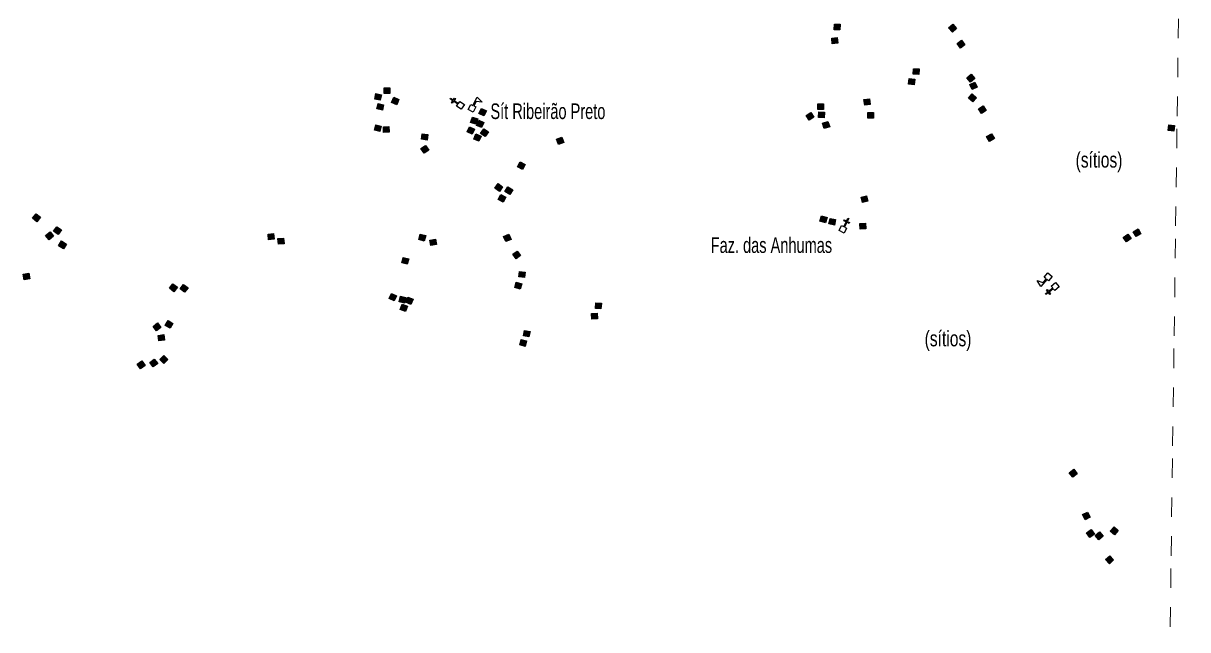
# Model space of a CAD drawing. Extents: x 679 to 705, y 7427.4 to 7455.4.
# Drawn here: x 698.81 to 704.8, y 7433.76 to 7436.88 of the extents above; entities that cross this region are included whole.
import ezdxf

# ---------------------------------------------------------------- set-up
doc = ezdxf.new("R2010")
doc.units = 0
doc.header["$LTSCALE"] = 0.032
doc.linetypes.add('SHORT_DASHED', pattern=[2.7, 1.5, -1.2])
for name, color, linetype, lineweight in [('2', 7, 'Continuous', 25), ('4', 7, 'Continuous', 25), ('58', 7, 'SHORT_DASHED', 13), ('6', 7, 'Continuous', 25)]:
    doc.layers.add(name, color=color, linetype=linetype, lineweight=lineweight)
doc.layers.add('61', color=7, linetype='Continuous')

msp = doc.modelspace()

# ---------------------------------------------------------------- hatches: boundary and pattern name
at = {"layer": '2'}
for points in [[(703.0125, 7436.8742), (703.0116, 7436.8452), (702.9826, 7436.8461), (702.9835, 7436.8751)], [(703.592, 7436.8745), (703.6113, 7436.8529), (703.5897, 7436.8335), (703.5704, 7436.8551)], [(702.9982, 7436.8054), (703.0006, 7436.7765), (702.9717, 7436.7741), (702.9693, 7436.803)], [(703.6374, 7436.7914), (703.6546, 7436.768), (703.6312, 7436.7508), (703.614, 7436.7742)], [(703.4182, 7436.6445), (703.417, 7436.6155), (703.388, 7436.6167), (703.3892, 7436.6456)], [(703.6862, 7436.6167), (703.7053, 7436.5949), (703.6834, 7436.5758), (703.6643, 7436.5977)], [(700.6981, 7436.5466), (700.6981, 7436.5176), (700.6691, 7436.5176), (700.6691, 7436.5466)], [(703.3971, 7436.5908), (703.3927, 7436.5622), (703.3641, 7436.5665), (703.3684, 7436.5952)], [(703.7056, 7436.5763), (703.7178, 7436.55), (703.6915, 7436.5378), (703.6793, 7436.5641)], [(700.6542, 7436.5114), (700.6486, 7436.4829), (700.6201, 7436.4886), (700.6258, 7436.5171)], [(700.7448, 7436.4865), (700.733, 7436.46), (700.7065, 7436.4718), (700.7183, 7436.4983)], [(703.1634, 7436.4909), (703.1678, 7436.4622), (703.1392, 7436.4578), (703.1348, 7436.4865)], [(703.6923, 7436.5155), (703.7138, 7436.4961), (703.6944, 7436.4745), (703.6729, 7436.4939)], [(700.6657, 7436.4604), (700.6594, 7436.4321), (700.6311, 7436.4385), (700.6375, 7436.4667)], [(701.1683, 7436.4413), (701.1943, 7436.4284), (701.1813, 7436.4024), (701.1553, 7436.4154)], [(702.8621, 7436.421), (702.8781, 7436.3969), (702.854, 7436.3808), (702.8379, 7436.4049)], [(702.9268, 7436.4651), (702.9268, 7436.4361), (702.8978, 7436.4361), (702.8978, 7436.4651)], [(702.9318, 7436.4221), (702.9301, 7436.3931), (702.9012, 7436.3948), (702.9029, 7436.4238)], [(703.184, 7436.4201), (703.184, 7436.3911), (703.155, 7436.3911), (703.155, 7436.4201)], [(703.7477, 7436.4548), (703.7638, 7436.4306), (703.7396, 7436.4145), (703.7236, 7436.4387)], [(700.6532, 7436.3505), (700.6465, 7436.3223), (700.6183, 7436.329), (700.625, 7436.3572)], [(701.1222, 7436.3967), (701.1497, 7436.3875), (701.1406, 7436.36), (701.1131, 7436.3692)], [(701.1547, 7436.3805), (701.1813, 7436.369), (701.1697, 7436.3424), (701.1431, 7436.3539)], [(702.9498, 7436.3744), (702.959, 7436.3469), (702.9315, 7436.3378), (702.9223, 7436.3653)], [(704.7321, 7436.3536), (704.7284, 7436.3248), (704.6996, 7436.3285), (704.7033, 7436.3573)], [(700.6933, 7436.3475), (700.6945, 7436.3186), (700.6656, 7436.3173), (700.6644, 7436.3463)], [(700.8936, 7436.307), (700.8895, 7436.2783), (700.8607, 7436.2824), (700.8648, 7436.3111)], [(701.1076, 7436.3471), (701.1338, 7436.3344), (701.1211, 7436.3083), (701.095, 7436.3209)], [(701.1404, 7436.3101), (701.1671, 7436.299), (701.156, 7436.2722), (701.1292, 7436.2833)], [(701.1807, 7436.3366), (701.2046, 7436.3202), (701.1882, 7436.2963), (701.1643, 7436.3127)], [(703.7907, 7436.3112), (703.8057, 7436.2863), (703.7808, 7436.2714), (703.7659, 7436.2963)], [(700.8817, 7436.2509), (700.8978, 7436.2268), (700.8737, 7436.2107), (700.8576, 7436.2348)], [(701.5818, 7436.2931), (701.5916, 7436.2658), (701.5643, 7436.256), (701.5545, 7436.2833)], [(701.3685, 7436.1673), (701.3939, 7436.1533), (701.38, 7436.1279), (701.3546, 7436.1418)], [(701.254, 7436.0553), (701.2777, 7436.0386), (701.261, 7436.0149), (701.2373, 7436.0316)], [(701.2686, 7435.9985), (701.2941, 7435.9848), (701.2804, 7435.9592), (701.2549, 7435.9729)], [(701.3048, 7436.0382), (701.3295, 7436.023), (701.3144, 7435.9983), (701.2896, 7436.0134)], [(703.1488, 7435.9926), (703.1559, 7435.9644), (703.1277, 7435.9574), (703.1207, 7435.9855)], [(698.879, 7435.8994), (698.9017, 7435.8814), (698.8836, 7435.8587), (698.8609, 7435.8767)], [(702.9453, 7435.8811), (702.9368, 7435.8534), (702.9091, 7435.8619), (702.9176, 7435.8896)], [(698.986, 7435.8332), (699.0098, 7435.8165), (698.9931, 7435.7928), (698.9694, 7435.8094)], [(702.9896, 7435.8697), (702.9831, 7435.8414), (702.9548, 7435.8478), (702.9613, 7435.8761)], [(703.1431, 7435.8515), (703.1453, 7435.8226), (703.1164, 7435.8204), (703.1142, 7435.8493)], [(704.5444, 7435.8217), (704.559, 7435.7966), (704.5339, 7435.782), (704.5193, 7435.8071)], [(698.9508, 7435.8067), (698.9689, 7435.7841), (698.9462, 7435.7659), (698.9281, 7435.7886)], [(699.0106, 7435.7599), (699.0349, 7435.7442), (699.0193, 7435.7198), (698.9949, 7435.7355)], [(700.1004, 7435.7985), (700.1035, 7435.7696), (700.0747, 7435.7665), (700.0716, 7435.7953)], [(700.1514, 7435.7742), (700.1537, 7435.7453), (700.1248, 7435.743), (700.1225, 7435.7719)], [(700.8824, 7435.7872), (700.8743, 7435.7593), (700.8465, 7435.7674), (700.8545, 7435.7952)], [(700.9326, 7435.7697), (700.9377, 7435.7412), (700.9092, 7435.7361), (700.904, 7435.7646)], [(701.3097, 7435.7942), (701.3208, 7435.7673), (701.294, 7435.7563), (701.2829, 7435.7831)], [(704.4918, 7435.7954), (704.509, 7435.772), (704.4856, 7435.7548), (704.4684, 7435.7782)], [(701.3532, 7435.7082), (701.3701, 7435.6846), (701.3466, 7435.6677), (701.3296, 7435.6912)], [(700.795, 7435.6681), (700.7877, 7435.6401), (700.7596, 7435.6474), (700.7669, 7435.6754)], [(698.842, 7435.5938), (698.8466, 7435.5651), (698.8179, 7435.5606), (698.8134, 7435.5892)], [(701.3935, 7435.6), (701.39, 7435.5712), (701.3612, 7435.5746), (701.3647, 7435.6034)], [(699.5826, 7435.5394), (699.6056, 7435.5219), (699.5881, 7435.4988), (699.565, 7435.5164)], [(699.6378, 7435.5367), (699.6605, 7435.5186), (699.6423, 7435.4959), (699.6197, 7435.5141)], [(701.3756, 7435.5398), (701.3676, 7435.5119), (701.3397, 7435.5199), (701.3477, 7435.5477)], [(700.6941, 7435.4639), (700.7062, 7435.4903), (700.7325, 7435.4782), (700.7204, 7435.4518)], [(700.7806, 7435.4685), (700.7736, 7435.4403), (700.7454, 7435.4474), (700.7525, 7435.4755)], [(700.8171, 7435.4603), (700.8059, 7435.4335), (700.7791, 7435.4447), (700.7903, 7435.4714)], [(700.7887, 7435.4244), (700.7785, 7435.3972), (700.7514, 7435.4074), (700.7615, 7435.4345)], [(701.7851, 7435.4401), (701.7832, 7435.4111), (701.7543, 7435.413), (701.7562, 7435.4419)], [(699.5576, 7435.3503), (699.5829, 7435.3362), (699.5689, 7435.3108), (699.5435, 7435.3249)], [(701.7642, 7435.3879), (701.765, 7435.3589), (701.736, 7435.3581), (701.7352, 7435.3871)], [(699.5035, 7435.3383), (699.5213, 7435.3154), (699.4984, 7435.2976), (699.4806, 7435.3205)], [(701.4185, 7435.2947), (701.413, 7435.2663), (701.3845, 7435.2718), (701.39, 7435.3003)], [(699.5353, 7435.2784), (699.5393, 7435.2497), (699.5105, 7435.2458), (699.5066, 7435.2745)], [(701.401, 7435.2457), (701.3933, 7435.2177), (701.3654, 7435.2254), (701.373, 7435.2534)], [(699.5362, 7435.1711), (699.5567, 7435.1506), (699.5362, 7435.1301), (699.5157, 7435.1506)], [(699.4226, 7435.1428), (699.4397, 7435.1194), (699.4162, 7435.1023), (699.3992, 7435.1258)], [(699.4867, 7435.1527), (699.5044, 7435.1298), (699.4815, 7435.1121), (699.4637, 7435.135)], [(704.2138, 7434.5859), (704.2314, 7434.5629), (704.2085, 7434.5452), (704.1908, 7434.5682)], [(704.285, 7434.3657), (704.2978, 7434.3396), (704.2717, 7434.3269), (704.259, 7434.353)], [(704.303, 7434.2765), (704.3198, 7434.2528), (704.2962, 7434.236), (704.2794, 7434.2596)], [(704.3466, 7434.264), (704.3651, 7434.2416), (704.3427, 7434.2231), (704.3242, 7434.2455)], [(704.4207, 7434.2907), (704.4426, 7434.2716), (704.4235, 7434.2497), (704.4016, 7434.2688)], [(704.3989, 7434.1415), (704.4186, 7434.1202), (704.3973, 7434.1006), (704.3776, 7434.1219)]]:
    msp.add_hatch(color=256, dxfattribs=at).paths.add_polyline_path(points)

# ---------------------------------------------------------------- linework, layer by layer
for points in [[(703.0125, 7436.8742), (703.0116, 7436.8452), (702.9826, 7436.8461), (702.9835, 7436.8751)], [(703.592, 7436.8745), (703.6113, 7436.8529), (703.5897, 7436.8335), (703.5704, 7436.8551)], [(702.9982, 7436.8054), (703.0006, 7436.7765), (702.9717, 7436.7741), (702.9693, 7436.803)], [(703.6374, 7436.7914), (703.6546, 7436.768), (703.6312, 7436.7508), (703.614, 7436.7742)], [(703.4182, 7436.6445), (703.417, 7436.6155), (703.388, 7436.6167), (703.3892, 7436.6456)], [(703.6862, 7436.6167), (703.7053, 7436.5949), (703.6834, 7436.5758), (703.6643, 7436.5977)], [(700.6981, 7436.5466), (700.6981, 7436.5176), (700.6691, 7436.5176), (700.6691, 7436.5466)], [(703.3971, 7436.5908), (703.3927, 7436.5622), (703.3641, 7436.5665), (703.3684, 7436.5952)], [(703.7056, 7436.5763), (703.7178, 7436.55), (703.6915, 7436.5378), (703.6793, 7436.5641)], [(700.6542, 7436.5114), (700.6486, 7436.4829), (700.6201, 7436.4886), (700.6258, 7436.5171)], [(700.7448, 7436.4865), (700.733, 7436.46), (700.7065, 7436.4718), (700.7183, 7436.4983)], [(703.1634, 7436.4909), (703.1678, 7436.4622), (703.1392, 7436.4578), (703.1348, 7436.4865)], [(703.6923, 7436.5155), (703.7138, 7436.4961), (703.6944, 7436.4745), (703.6729, 7436.4939)], [(700.6657, 7436.4604), (700.6594, 7436.4321), (700.6311, 7436.4385), (700.6375, 7436.4667)], [(701.1683, 7436.4413), (701.1943, 7436.4284), (701.1813, 7436.4024), (701.1553, 7436.4154)], [(702.8621, 7436.421), (702.8781, 7436.3969), (702.854, 7436.3808), (702.8379, 7436.4049)], [(702.9268, 7436.4651), (702.9268, 7436.4361), (702.8978, 7436.4361), (702.8978, 7436.4651)], [(702.9318, 7436.4221), (702.9301, 7436.3931), (702.9012, 7436.3948), (702.9029, 7436.4238)], [(703.184, 7436.4201), (703.184, 7436.3911), (703.155, 7436.3911), (703.155, 7436.4201)], [(703.7477, 7436.4548), (703.7638, 7436.4306), (703.7396, 7436.4145), (703.7236, 7436.4387)], [(700.6532, 7436.3505), (700.6465, 7436.3223), (700.6183, 7436.329), (700.625, 7436.3572)], [(701.1222, 7436.3967), (701.1497, 7436.3875), (701.1406, 7436.36), (701.1131, 7436.3692)], [(701.1547, 7436.3805), (701.1813, 7436.369), (701.1697, 7436.3424), (701.1431, 7436.3539)], [(702.9498, 7436.3744), (702.959, 7436.3469), (702.9315, 7436.3378), (702.9223, 7436.3653)], [(704.7321, 7436.3536), (704.7284, 7436.3248), (704.6996, 7436.3285), (704.7033, 7436.3573)], [(700.6933, 7436.3475), (700.6945, 7436.3186), (700.6656, 7436.3173), (700.6644, 7436.3463)], [(700.8936, 7436.307), (700.8895, 7436.2783), (700.8607, 7436.2824), (700.8648, 7436.3111)], [(701.1076, 7436.3471), (701.1338, 7436.3344), (701.1211, 7436.3083), (701.095, 7436.3209)], [(701.1404, 7436.3101), (701.1671, 7436.299), (701.156, 7436.2722), (701.1292, 7436.2833)], [(701.1807, 7436.3366), (701.2046, 7436.3202), (701.1882, 7436.2963), (701.1643, 7436.3127)], [(703.7907, 7436.3112), (703.8057, 7436.2863), (703.7808, 7436.2714), (703.7659, 7436.2963)], [(700.8817, 7436.2509), (700.8978, 7436.2268), (700.8737, 7436.2107), (700.8576, 7436.2348)], [(701.5818, 7436.2931), (701.5916, 7436.2658), (701.5643, 7436.256), (701.5545, 7436.2833)], [(701.3685, 7436.1673), (701.3939, 7436.1533), (701.38, 7436.1279), (701.3546, 7436.1418)], [(701.254, 7436.0553), (701.2777, 7436.0386), (701.261, 7436.0149), (701.2373, 7436.0316)], [(701.2686, 7435.9985), (701.2941, 7435.9848), (701.2804, 7435.9592), (701.2549, 7435.9729)], [(701.3048, 7436.0382), (701.3295, 7436.023), (701.3144, 7435.9983), (701.2896, 7436.0134)], [(703.1488, 7435.9926), (703.1559, 7435.9644), (703.1277, 7435.9574), (703.1207, 7435.9855)], [(698.879, 7435.8994), (698.9017, 7435.8814), (698.8836, 7435.8587), (698.8609, 7435.8767)], [(702.9453, 7435.8811), (702.9368, 7435.8534), (702.9091, 7435.8619), (702.9176, 7435.8896)], [(698.986, 7435.8332), (699.0098, 7435.8165), (698.9931, 7435.7928), (698.9694, 7435.8094)], [(702.9896, 7435.8697), (702.9831, 7435.8414), (702.9548, 7435.8478), (702.9613, 7435.8761)], [(703.1431, 7435.8515), (703.1453, 7435.8226), (703.1164, 7435.8204), (703.1142, 7435.8493)], [(704.5444, 7435.8217), (704.559, 7435.7966), (704.5339, 7435.782), (704.5193, 7435.8071)], [(698.9508, 7435.8067), (698.9689, 7435.7841), (698.9462, 7435.7659), (698.9281, 7435.7886)], [(699.0106, 7435.7599), (699.0349, 7435.7442), (699.0193, 7435.7198), (698.9949, 7435.7355)], [(700.1004, 7435.7985), (700.1035, 7435.7696), (700.0747, 7435.7665), (700.0716, 7435.7953)], [(700.1514, 7435.7742), (700.1537, 7435.7453), (700.1248, 7435.743), (700.1225, 7435.7719)], [(700.8824, 7435.7872), (700.8743, 7435.7593), (700.8465, 7435.7674), (700.8545, 7435.7952)], [(700.9326, 7435.7697), (700.9377, 7435.7412), (700.9092, 7435.7361), (700.904, 7435.7646)], [(701.3097, 7435.7942), (701.3208, 7435.7673), (701.294, 7435.7563), (701.2829, 7435.7831)], [(704.4918, 7435.7954), (704.509, 7435.772), (704.4856, 7435.7548), (704.4684, 7435.7782)], [(701.3532, 7435.7082), (701.3701, 7435.6846), (701.3466, 7435.6677), (701.3296, 7435.6912)], [(700.795, 7435.6681), (700.7877, 7435.6401), (700.7596, 7435.6474), (700.7669, 7435.6754)], [(698.842, 7435.5938), (698.8466, 7435.5651), (698.8179, 7435.5606), (698.8134, 7435.5892)], [(701.3935, 7435.6), (701.39, 7435.5712), (701.3612, 7435.5746), (701.3647, 7435.6034)], [(699.5826, 7435.5394), (699.6056, 7435.5219), (699.5881, 7435.4988), (699.565, 7435.5164)], [(699.6378, 7435.5367), (699.6605, 7435.5186), (699.6423, 7435.4959), (699.6197, 7435.5141)], [(701.3756, 7435.5398), (701.3676, 7435.5119), (701.3397, 7435.5199), (701.3477, 7435.5477)], [(700.6941, 7435.4639), (700.7062, 7435.4903), (700.7325, 7435.4782), (700.7204, 7435.4518)], [(700.7806, 7435.4685), (700.7736, 7435.4403), (700.7454, 7435.4474), (700.7525, 7435.4755)], [(700.8171, 7435.4603), (700.8059, 7435.4335), (700.7791, 7435.4447), (700.7903, 7435.4714)], [(700.7887, 7435.4244), (700.7785, 7435.3972), (700.7514, 7435.4074), (700.7615, 7435.4345)], [(701.7851, 7435.4401), (701.7832, 7435.4111), (701.7543, 7435.413), (701.7562, 7435.4419)], [(699.5576, 7435.3503), (699.5829, 7435.3362), (699.5689, 7435.3108), (699.5435, 7435.3249)], [(701.7642, 7435.3879), (701.765, 7435.3589), (701.736, 7435.3581), (701.7352, 7435.3871)], [(699.5035, 7435.3383), (699.5213, 7435.3154), (699.4984, 7435.2976), (699.4806, 7435.3205)], [(701.4185, 7435.2947), (701.413, 7435.2663), (701.3845, 7435.2718), (701.39, 7435.3003)], [(699.5353, 7435.2784), (699.5393, 7435.2497), (699.5105, 7435.2458), (699.5066, 7435.2745)], [(701.401, 7435.2457), (701.3933, 7435.2177), (701.3654, 7435.2254), (701.373, 7435.2534)], [(699.5362, 7435.1711), (699.5567, 7435.1506), (699.5362, 7435.1301), (699.5157, 7435.1506)], [(699.4226, 7435.1428), (699.4397, 7435.1194), (699.4162, 7435.1023), (699.3992, 7435.1258)], [(699.4867, 7435.1527), (699.5044, 7435.1298), (699.4815, 7435.1121), (699.4637, 7435.135)], [(704.2138, 7434.5859), (704.2314, 7434.5629), (704.2085, 7434.5452), (704.1908, 7434.5682)], [(704.285, 7434.3657), (704.2978, 7434.3396), (704.2717, 7434.3269), (704.259, 7434.353)], [(704.303, 7434.2765), (704.3198, 7434.2528), (704.2962, 7434.236), (704.2794, 7434.2596)], [(704.3466, 7434.264), (704.3651, 7434.2416), (704.3427, 7434.2231), (704.3242, 7434.2455)], [(704.4207, 7434.2907), (704.4426, 7434.2716), (704.4235, 7434.2497), (704.4016, 7434.2688)], [(704.3989, 7434.1415), (704.4186, 7434.1202), (704.3973, 7434.1006), (704.3776, 7434.1219)]]:
    msp.add_lwpolyline(points, close=True, dxfattribs=at)
at = {"layer": '4'}
for points in [[(701.1248, 7436.4563), (701.1465, 7436.4996), (701.1716, 7436.4741), (701.1409, 7436.4775), (701.1292, 7436.4541)], [(701.1292, 7436.4541), (701.14, 7436.4487), (701.127, 7436.4228), (701.1011, 7436.4358), (701.1141, 7436.4617), (701.1248, 7436.4563)], [(704.0716, 7435.5658), (704.0624, 7435.5737), (704.0813, 7435.5957), (704.1033, 7435.5768), (704.0844, 7435.5548), (704.0753, 7435.5626)], [(704.0753, 7435.5626), (704.0438, 7435.5259), (704.0256, 7435.5567), (704.0546, 7435.546), (704.0716, 7435.5658)]]:
    msp.add_lwpolyline(points, dxfattribs=at)
at = {"layer": '58'}
msp.add_lwpolyline([(704.6209, 7427.3609), (704.6287, 7427.926), (704.6365, 7428.491), (704.6443, 7429.0561), (704.652, 7429.6212), (704.6598, 7430.1862), (704.6676, 7430.7513), (704.6754, 7431.3163), (704.6832, 7431.8814), (704.6909, 7432.4465), (704.6987, 7433.0115), (704.7065, 7433.5766), (704.7143, 7434.1416), (704.722, 7434.7067), (704.7298, 7435.2717), (704.7376, 7435.8368), (704.7453, 7436.4019), (704.7531, 7436.9669), (704.7608, 7437.532), (704.7686, 7438.097), (704.7764, 7438.6621), (704.7841, 7439.2271), (704.7919, 7439.7922), (704.7996, 7440.3572)], dxfattribs=at)
at = {"layer": '6'}
for points in [[(701.0479, 7436.4629), (701.0253, 7436.478), (701.0186, 7436.4679), (701.0145, 7436.4706), (701.0213, 7436.4807), (701.0076, 7436.4898), (701.0103, 7436.4938), (701.0239, 7436.4847), (701.0306, 7436.4947), (701.0347, 7436.492), (701.028, 7436.4819), (701.0505, 7436.4669)], [(701.0505, 7436.4669), (701.0573, 7436.477), (701.0814, 7436.4609), (701.0653, 7436.4368), (701.0412, 7436.4529), (701.0479, 7436.4629)], [(703.0354, 7435.8316), (703.0462, 7435.8262), (703.0333, 7435.8003), (703.0073, 7435.8132), (703.0203, 7435.8392), (703.0311, 7435.8337)], [(703.0311, 7435.8337), (703.0433, 7435.858), (703.0324, 7435.8634), (703.0346, 7435.8678), (703.0455, 7435.8624), (703.0528, 7435.877), (703.0571, 7435.8749), (703.0497, 7435.8602), (703.0606, 7435.8548), (703.0584, 7435.8504), (703.0476, 7435.8558), (703.0354, 7435.8316)], [(704.1054, 7435.5183), (704.0977, 7435.5276), (704.1202, 7435.546), (704.1385, 7435.5235), (704.116, 7435.5052), (704.1084, 7435.5145)], [(704.1084, 7435.5145), (704.0874, 7435.4974), (704.095, 7435.488), (704.0912, 7435.4849), (704.0836, 7435.4943), (704.0709, 7435.484), (704.0678, 7435.4877), (704.0805, 7435.498), (704.0729, 7435.5074), (704.0767, 7435.5105), (704.0843, 7435.5011), (704.1054, 7435.5183)]]:
    msp.add_lwpolyline(points, dxfattribs=at)

# ---------------------------------------------------------------- texts
at = {"layer": '61'}
for s, width, p in [('Sít Ribeirão Preto', 0.7, (701.215, 7436.3867)), ('(sítios)', 0.75, (704.2233, 7436.1371)), ('Faz. das Anhumas', 0.7, (702.3472, 7435.6984)), ('(sítios)', 0.75, (703.4471, 7435.2182))]:
    msp.add_text(s, height=0.08, dxfattribs=dict(at, width=width)).set_placement(p)

doc.saveas('drawing.dxf')
